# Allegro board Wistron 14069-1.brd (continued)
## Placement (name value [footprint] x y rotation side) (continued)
C9315  SCD22U16V2KX-GP  [C402H22]  83.73 87.94 0 top
C9316  SCD22U16V2KX-GP  [C402H22]  82.72 87.94 0 top
C9317  SCD22U16V2KX-GP  [C402H22]  87.75 87.94 0 top
C9318  SCD22U16V2KX-GP  [C402H22]  86.73 87.94 0 top
C9319  SCD22U16V2KX-GP  [C402H22]  91.78 87.94 0 top
C9320  SCD22U16V2KX-GP  [C402H22]  90.76 87.94 0 top
C9321  SCD1U16V2KX-3GP  [C402H22]  54.42 71.43 0 top
C9322  SCD1U16V2KX-3GP  [C402H22]  55.44 71.43 0 top
C9323  SCD22U16V2KX-GP  [C402H22]  95.8 87.57 0 top
C9324  SCD22U16V2KX-GP  [C402H22]  94.79 87.57 0 top
C9325  SCD22U16V2KX-GP  [C402H22]  101.78 87.94 0 top
C9326  SCD22U16V2KX-GP  [C402H22]  100.76 87.94 0 top
C9327  SCD22U16V2KX-GP  [C402H22]  105.7 87.94 0 top
C9328  SCD22U16V2KX-GP  [C402H22]  104.68 87.94 0 top
C9329  SCD1U16V2KX-3GP  [C402H22]  52.89 86.52 180 top
C9330  SCD1U16V2KX-3GP  [C402H22]  53.87 70.02 90 top
C9331  SCD22U16V2KX-GP  [C402H22]  109.74 87.94 0 top
C9332  SCD22U16V2KX-GP  [C402H22]  108.72 87.94 0 top
C9333  SCD22U16V2KX-GP  [C402H22]  113.7 87.94 0 top
C9334  SCD22U16V2KX-GP  [C402H22]  112.68 87.94 0 top
C9335  SCD22U16V2KX-GP  [C402H22]  116.72 87.94 0 top
C9336  SCD22U16V2KX-GP  [C402H22]  117.73 87.94 0 top
C9337  SCD22U16V2KX-GP  [C402H22]  121.79 87.94 0 top
C9338  SCD22U16V2KX-GP  [C402H22]  120.77 87.94 0 top
C9339  SCD22U16V2KX-GP  [C402H22]  124.62 87.94 0 top
C9340  SCD22U16V2KX-GP  [C402H22]  125.64 87.94 0 top
C9402  SCD1U25V3KX-GP  [C603H36]  42.62 50.05 270 top
C9403  SCD1U25V3KX-GP  [C603H36]  42.62 48.78 270 top
C9404  SCD1U16V2KX-3GP  [C402H22]  56.15 30.96 270 top
C9405  SCD1U16V2KX-3GP  [C402H22]  56.15 29.94 270 top
C9406  SCD1U16V2KX-3GP  [C402H22]  54.18 30.56 90 top
C9407  SCD1U16V2KX-3GP  [C402H22]  54.32 49.45 90 top
C9408  SCD1U16V2KX-3GP  [C402H22]  54.32 50.34 90 top
C9409  SCD1U16V2KX-3GP  [C402H22]  54.16 28.81 90 top
C9410  SCD1U16V2KX-3GP  [C402H22]  53.1 12.55 0 top
C9411  SCD1U16V2KX-3GP  [C402H22]  54.01 12.55 0 top
C9412  SCD1U16V2KX-3GP  [C402H22]  54.89 12.55 0 top
C9413  SCD1U25V3KX-GP  [C603H36]  37.5 17.68 270 top
C9414  SCD1U25V3KX-GP  [C603H36]  37.5 18.95 270 top
C9415  SCD1U16V2KX-3GP  [C402H22]  54.19 29.69 90 top
C9420  SC10P50V2JN-4GP  [C402H22]  221.79 10.74 270 top
C9422  SC10P50V2JN-4GP  [C402H22]  147.88 94.51 0 top
C9902  SCD1U16V2KX-3GP  [C402H22]  47.52 88.82 180 top
C15159  SCD1U16V2ZY-2GP  [C402H22]  193.32 76.78 180 top
C15160  SC1U16V2KX-GP  [C402H22]  187.66 84.84 180 top
C15161  SC1U16V2KX-GP  [C402H22]  190.96 84.81 180 top
CMOS1  PIN-CON3-S-GP  [21S-91-03GB01]  186 7.63 270 top
CPU1  SKYLAKE-1  [SKTBGA1151R754612-UH369]  123.98 163.95 90 top
CRF1  PIN-CON5-SFP2-GP-U  [210-91-05GY21-U]  91 5.5 0 top
D4  SDMK0340L-7-F-GP  [SOD323AKH42]  216.82 50.7 90 top
D20  BAT54A-7-F-2-GP  [SOT23-2D4-312H48]  115.07 33.25 0 top
D21  BAT54A-7-F-2-GP  [SOT23-2D4-312H48]  128.22 30.91 0 top
D2502  BAS40C-2-GP  [SOT-23-9H44]  103.84 19.38 270 top
D2601  1SS355-4-GP  [SOD323AKH38]  145.6 231.88 90 top
D2602  1SS355GP-GP  [SOD323AKH40]  212.3 238.53 270 top
D2603  1SS355GP-GP  [SOD323AKH40]  231.46 36.71 0 top
D2702  DF2B6D8E-1-GP  [D1608AK-UH28]  6.14 47.06 0 top
D2906  BAT54A-7-F-2-GP  [SOT23-2D4-312H48]  13.44 18.05 0 top
D2907  BAT54A-7-F-2-GP  [SOT23-2D4-312H48]  26.34 19.14 0 top
D3001  AZ5125-01H-R7G-GP  [SOD-523-4H28]  9.87 69.52 0 top
D3002  AZ5125-02S-R7G-1-GP  [SOT23-2D4-312H46]  18.49 71.04 0 top
D3003  AZ5125-02S-R7G-1-GP  [SOT23-2D4-312H46]  7.01 69.56 0 top
D3004  AZ5125-01H-R7G-GP  [SOD-523-4H28]  15.62 69.77 0 top
D3005  AZ5125-02S-R7G-1-GP  [SOT23-2D4-312H46]  12.73 69.67 0 top
D3006  AZ5125-01H-R7G-GP  [SOD-523-4H28]  19.14 73.99 90 top
D5601  1SS355-4-GP  [SOD323AKH38]  24.11 228.86 0 top
DBGH1  PIN-CONN14A-SFP1-GP  [220-47-07GB22]  228 105 270 top
DIMM1  DDR4-288P-82-GP  [AH08847-A9L2-4M]  184.43 163.97 270 top
DIMM2  DDR4-288P-82-GP  [AH08847-A9L2-4M]  204.13 163.97 270 top
DIMM3  DDR4-288P-82-GP  [AH08847-A9L2-4M]  176.03 163.97 270 top
DIMM4  DDR4-288P-82-GP  [AH08847-A9L2-4M]  195.73 163.97 270 top
DP1  SKT-DISPLAY20P-25-GP  [105020-0001]  4.2 195 270 top
EC3801  SCD1U16V2KX-3GP  [C402H22]  24.16 170.94 270 top
EC3802  SCD1U16V2KX-3GP  [C402H22]  25.56 152.43 270 top
EC3803  SCD1U16V2KX-3GP  [C402H22]  25.56 153.32 270 top
EC3804  SCD1U16V2KX-3GP  [C402H22]  24.16 171.83 270 top
EC3805  SCD1U16V2KX-3GP  [C402H22]  25.63 150.44 270 top
EC3806  SCD1U16V2KX-3GP  [C402H22]  24.17 173.36 270 top
EC3807  SCD1U16V2KX-3GP  [C402H22]  25.63 149.55 270 top
EC3808  SCD1U16V2KX-3GP  [C402H22]  24.17 174.25 270 top
EC3901  SCD1U16V2KX-3GP  [C402H22]  145.77 20.13 0 top
EC3902  SCD1U16V2KX-3GP  [C402H22]  143.36 20.13 0 top
EC3903  SCD1U16V2KX-3GP  [C402H22]  144.25 20.13 0 top
EC3904  SCD1U16V2KX-3GP  [C402H22]  146.66 20.13 0 top
ED3201  AZC099-04S-R7G-GP  [SOT-6H58]  29.68 114.39 90 top
ED3203  AZC099-04S-R7G-GP  [SOT-6H58]  29.68 118.7 90 top
ED3204  AZC099-04S-R7G-GP  [SOT-6H58]  29.35 105.4 270 top
ED5601  AZ1045-04F-R7G-GP  [DFN10G2510H26]  15.93 218.36 270 top
ED5602  AZ1045-04F-R7G-GP  [DFN10G2510H26]  15.93 213.46 270 top
ED5603  AZ1045-04F-R7G-GP  [DFN10G2510H26]  15.9 225.03 270 top
ED5701  AZ1045-04F-R7G-GP  [DFN10G2510H26]  15.62 195.86 270 top
ED5702  AZ1045-04F-R7G-GP  [DFN10G2510H26]  16.55 191.5 270 top
ED5703  AZ1045-04F-R7G-GP  [DFN10G2510H26]  16.55 187.44 90 top
EL3201  MCM1012B900FBP-GP-U  [L125100-4P-1H37]  33.74 117.69 180 top
EL3202  MCM1012B900FBP-GP-U  [L125100-4P-1H37]  33.74 119.85 180 top
EL3203  MCM1012B900FBP-GP-U  [L125100-4P-1H37]  33.74 115.53 180 top
EL3204  MCM1012B900FBP-GP-U  [L125100-4P-1H37]  33.74 113.37 180 top
EL3603  FILTER-4P-184-GP  [L125100-4P-4H28]  33.77 110.65 180 top
EL3604  FILTER-4P-184-GP  [L125100-4P-4H28]  33.77 108.24 180 top
EL3605  FILTER-4P-184-GP  [L125100-4P-4H28]  162.41 102.15 270 top
EL3701  FILTER-4P-184-GP  [L125100-4P-4H28]  107.29 19.56 270 top
EL3702  FILTER-4P-184-GP  [L125100-4P-4H28]  109.57 19.56 270 top
EL3703  FILTER-4P-184-GP  [L125100-4P-4H28]  87.58 19.41 270 top
EL3801  FILTER-4P-98-GP  [L125100-4P-5H24]  21.52 171.46 270 top
EL3802  MCM1012B900FBP-GP-U  [L125100-4P-1H37]  23.51 169.1 0 top
EL3803  FILTER-4P-98-GP  [L125100-4P-5H24]  21.82 152.43 270 top
EL3804  FILTER-4P-98-GP  [L125100-4P-5H24]  22.54 141.11 270 top
EL3805  MCM1012B900FBP-GP-U  [L125100-4P-1H37]  23.73 147.71 0 top
EL3806  FILTER-4P-98-GP  [L125100-4P-5H24]  22.32 164.72 270 top
EL3807  MCM1012B900FBP-GP-U  [L125100-4P-1H37]  23.73 145.55 0 top
EL3808  MCM1012B900FBP-GP-U  [L125100-4P-1H37]  23.51 166.94 0 top
EL3809  FILTER-4P-98-GP  [L125100-4P-5H24]  21.59 173.81 270 top
EL3810  FILTER-4P-98-GP  [L125100-4P-5H24]  21.75 150.07 270 top
EL3811  FILTER-4P-98-GP  [L125100-4P-5H24]  22.54 143.34 270 top
EL3812  FILTER-4P-98-GP  [L125100-4P-5H24]  22.31 162.49 270 top
EL3901  FILTER-4P-98-GP  [L125100-4P-5H24]  146.1 17.67 0 top
EL3902  FILTER-4P-98-GP  [L125100-4P-5H24]  143.81 17.67 0 top
EL3903  FILTER-4P-98-GP  [L125100-4P-5H24]  139.32 17.65 0 top
EL3904  FILTER-4P-184-GP  [L125100-4P-4H28]  148.28 19.75 270 top
EL3905  FILTER-4P-184-GP  [L125100-4P-4H28]  151.35 19.71 270 top
EL3906  FILTER-4P-98-GP  [L125100-4P-5H24]  141.6 17.65 0 top
EL5601  FILTER-4P-172-GP  [L125100-4PH26]  19.51 212.45 90 top
EL5602  FILTER-4P-172-GP  [L125100-4PH26]  19.51 214.6 90 top
EL5603  FILTER-4P-172-GP  [L125100-4PH26]  19.51 217.22 90 top
EL5604  FILTER-4P-172-GP  [L125100-4PH26]  19.51 219.38 90 top
EL6001  COIL-40OHM-GP  [L125100-4PH26]  221.37 41.53 180 top
EL6002  COIL-40OHM-GP  [L125100-4PH26]  221.37 35.81 180 top
EL6003  COIL-40OHM-GP  [L125100-4PH26]  221.39 27.69 180 top
EL6004  COIL-40OHM-GP  [L125100-4PH26]  221.49 21.08 180 top
EL6005  COIL-40OHM-GP  [L125100-4PH26]  209.65 38.23 180 top
EL6006  COIL-40OHM-GP  [L125100-4PH26]  210.69 44.07 180 top
EL6007  COIL-40OHM-GP  [L125100-4PH26]  210.44 23.11 180 top
EL6008  COIL-40OHM-GP  [L125100-4PH26]  211.18 28.78 180 top
F5601  POLYSW-1D5A8V-4-GP  [POLYSW-3217-UH40]  17.14 231.83 0 top
F5602  POLYSW-1D5A8V-4-GP  [POLYSW-3217-UH40]  12.19 207.52 0 top
FANC1  FOX-CON4-11-GP  [HF1004E]  151 236.82 0 top
FANS1  FOX-CON4-11-GP  [HF1004E]  221.73 237 0 top
FANS2  JWT-CON3-S2-GP  [A2543WV2-3P]  223 237 0 top
FANS3  FOX-CON4-11-GP  [HF1004E]  231 149 270 top
FL2906  0R0603-PAD-2-GP-U  [0R0603-PAD-1-U]  17.46 13.51 0 top
FL2907  0R0603-PAD-2-GP-U  [0R0603-PAD-1-U]  18.86 13.51 0 top
FL2908  0R0603-PAD-2-GP-U  [0R0603-PAD-1-U]  22.52 15.04 0 top
FL2909  0R0603-PAD-2-GP-U  [0R0603-PAD-1-U]  21.17 15.04 0 top
G7901  COPPER-CLOSE-GP-U  [CON2C-U]  234.27 49.01 180 top
GPIO1  JOWLE-CON2-5-GP  [A2541WV0-1EX2PA-6T]  67.3 6.82 90 top
GPIO2  JOWLE-CON2-5-GP  [A2541WV0-1EX2PA-6T]  61.62 6.79 90 top
H1  GENS315R158-8-F-A-GP  [GENS315R158-8-F-A]  33.02 237.65 180 top
H2  GENS315R158-8-F-A-GP  [GENS315R158-8-F-A]  165.1 237.65 180 top
H3  GENS315R158-8-F-A-GP  [GENS315R158-8-F-A]  237.49 237.65 180 top
H4  GENS315R158-8-F-A-GP  [GENS315R158-8-F-A]  237.47 80.17 180 top
H5  GENS315R158-8-F-A-GP  [GENS315R158-8-F-A]  165.1 80.17 180 top
H6  GENS315R158-8-F-A-GP  [GENS315R158-8-F-A]  10.16 80.17 180 top
H7  GENS315R158-8-F-A-GP  [GENS315R158-8-F-A]  10.16 34.45 180 top
H8  GENS315R158-8-F-A-GP  [GENS315R158-8-F-A]  165.1 14.13 180 top
HDMI1  SKT-HDMI23-49-GP  [SKT-HDMI23-150122-10]  3.5 223 270 top
HS1  STF256R109H99-GP  [STF256R109H99]  125.6 98 180 top
HS2  STF256R113-UH258-GP  [STF256R113-UH258]  64.25 58 180 top
HS3  STF256R113-UH258-GP  [STF256R113-UH258]  26.25 58 180 top
JP1  JOWLE-CON2-5-GP  [A2541WV0-1EX2PA-6T]  240.81 63.25 90 top
L2702  PBY201209T-221Y-N-GP  [L20125H44]  8.55 47.21 270 top
L2901  PBY201209T-800Y-N-1GP  [L20125H44]  46.2 10.84 90 top
L3001  MHC1608S601LBP-GP  [L603H38]  7.71 65.3 180 top
L3002  MHC1608S601LBP-GP  [L603H38]  19.18 66.7 180 top
L3003  MHC1608S601LBP-GP  [L603H38]  17.81 66.7 180 top
L3004  MHC1608S601LBP-GP  [L603H38]  13.33 65.4 180 top
L3005  MHC1608S601LBP-GP  [L603H38]  12.01 65.4 180 top
L3006  MHC1608S601LBP-GP  [L603H38]  6.39 65.3 180 top
L3101  COIL-4D7UH-13-GP  [L35301330H103]  31.68 91.59 90 top
L5601  MHC1608S181NBP-GP  [L603H38]  16.81 228.48 90 top
L6401  MHC1608S601LBP-GP  [L603H38]  232.37 11.17 270 top
L6801  FCM1608KFG-301T05-GP  [L1608-UH38]  205.21 10.13 270 top
L7901  MHC1608S181NBP-GP  [L603H38]  238.41 52.44 0 top
LEDH1  TCN-CONN14A-SFP-GP-U  [T11-0063-1A40-0-U]  210.08 6.5 0 top
LEDH2  PIN-CONN14A-SFP5-GP  [210-92-07GB11]  237 20.09 90 top
MECLR1  PIN-CON3-S-GP  [21S-91-03GB01]  196 7.63 270 top
NGFFE1  SKT-NGFF75P-91-GP  [AS0BC21-S40BE-7H]  153.85 98 270 top
NGFFM1  SKT-NGFF75P-90-GP-U  [AS0BC21-S85BM-7H]  103.85 58 270 top
NOREF  -  []  163.3 194.13 0 top
NOREF#2  -  [unnamed#2]  86.48 125.8 0 top
NOREF#3  -  []  94.31 146.66 0 top
NOREF#4  -  [unnamed#2]  52.4 121.45 0 top
NOREF#5  -  [unnamed#2]  161.48 200.8 0 top
NOREF#6  -  [unnamed#2]  140.14 29.37 0 top
NOREF#7  -  [unnamed#2]  239 5 0 top
NOREF#8  -  []  94.41 154.31 0 top
NOREF#9  *  [unnamed#2]  10.73 235.75 0 top
NOREF#10  -  [unnamed#2]  85.63 226.69 0 top
NOREF#11  *  [unnamed#2]  229.94 239.29 0 top
NOREF#12  -  [unnamed#2]  5 5 0 top
NOREF#13  -  []  0 0 0 top
NOREF#14  *  [unnamed#2]  8.54 18.66 0 top
NOREF#15  -  []  0 0 0 top
NOREF#16  -  []  161.14 225.48 0 top
NOREF#17  -  [unnamed#2]  5.59 237.74 0 top
NOREF#18  -  [unnamed#2]  161.48 125.8 0 top
NOREF#19  -  [unnamed#2]  164.14 66.37 0 top
NOREF#20  -  [unnamed#2]  52.4 220.26 0 top
NOREF#21  -  [unnamed#2]  139.57 226.69 0 top
NOREF#22  -  []  0 0 0 top
NOREF#23  -  [unnamed#2]  86.48 200.8 0 top
NOREF#24  -  []  154.48 213.16 180 top
NOREF#25  *  [unnamed#2]  8.54 18.66 180 bottom
NOREF#26  *  [unnamed#2]  229.94 239.29 180 bottom
NOREF#27  *  [unnamed#2]  10.73 235.75 180 bottom
PC301  SC1800P50V2KX-1GP  [C402H22]  183.51 85.34 180 top
PC4602  SC470P50V2KX-3GP  [C402H22]  73.05 216.92 0 top
PC4605  SCD01U50V2KX-1GP  [C402H22]  63.71 218.54 0 top
PC4606  SCD01U50V2KX-1GP  [C402H22]  66.11 214.25 270 top
PC4610  SC68P50V2JN-1GP  [C402H22]  74.13 218.34 270 top
PC4628  SCD01U50V2KX-1GP  [C402H22]  65.17 217.76 270 top
PC4630  SC68P50V2JN-1GP  [C402H22]  72.4 232.19 270 top
PC4631  SC470P50V2KX-3GP  [C402H22]  70.54 235.53 180 top
PC4632  SC2D2U6D3V2MX-GP  [C402H22]  78.27 231.65 90 top
PC4633  SCD01U50V2KX-1GP  [C402H22]  70.61 213.03 0 top
PC4634  SCD01U50V2KX-1GP  [C402H22]  64.59 234.15 270 top
PC4635  SC1U6D3V2KX-GP  [C402H22]  82.37 230.21 0 top
PC4636  SCD22U16V2KX-GP  [C402H22]  58.55 228.35 270 top
PC4637  SCD22U16V2KX-GP  [C402H22]  59.34 221.51 270 top
PC4639  SC180P50V2JN-1GP  [C402H22]  74.45 215 0 top
PC4640  SC180P50V2JN-1GP  [C402H22]  75.87 214.64 270 top
PC4641  SC180P50V2JN-1GP  [C402H22]  75.86 215.52 90 top
PC4642  SC180P50V2JN-1GP  [C402H22]  75.26 234.94 180 top
PC4643  SC180P50V2JN-1GP  [C402H22]  75.7 233.53 90 top
PC4644  SC180P50V2JN-1GP  [C402H22]  76.16 234.95 180 top
PC4645  SCD47U10V2KX-GP  [C402H22]  79.06 221.71 90 top
PC4646  SCD01U50V2KX-1GP  [C402H22]  70.6 234.14 90 top
PC4655  SC1U16V2KX-GP  [C402H22]  79.08 230.71 270 top
PC4666  SCD1U50V2KX-1-GP  [C402H22]  65.37 227.87 0 top
PC4701  SCD01U50V2KX-1GP  [C402H22]  43.43 191.38 270 top
PC4702  SC10U25V6KX-1GP  [C1206H71]  40.51 214.39 270 top
PC4703  SCD1U25V3KX-GP  [C603H36]  42.91 219.16 90 top
PC4704  SC1U16V2KX-GP  [C402H22]  50.12 215.98 180 top
PC4705  SC1KP50V2KX-1GP  [C402H22]  60.71 195.58 0 top
PC4706  SCD1U25V3KX-GP  [C603H36]  44.99 196.91 90 top
PC4707  SC10U25V6KX-1GP  [C1206H71]  43.43 193.09 270 top
PC4708  SC1U16V2KX-GP  [C402H22]  51.17 195.48 180 top
PC4709  SC1KP50V2KX-1GP  [C402H22]  60.63 173.99 0 top
PC4710  SCD1U25V3KX-GP  [C603H36]  44.99 174.96 90 top
PC4711  SC10U25V6KX-1GP  [C1206H71]  43.43 170.28 270 top
PC4712  SC1U16V2KX-GP  [C402H22]  51.04 173.76 180 top
PC4713  SC1KP50V2KX-1GP  [C402H22]  60.66 152.32 0 top
PC4716  SCD01U50V2KX-1GP  [C402H22]  40.51 212.65 270 top
PC4717  SCD01U50V2KX-1GP  [C402H22]  43.43 168.55 270 top
PC4720  SCD47U10V2KX-GP  [C402H22]  66.6 217.47 180 top
PC4721  SCD47U10V2KX-GP  [C402H22]  67.51 214.72 0 top
PC4722  SCD47U10V2KX-GP  [C402H22]  64.66 219.92 0 top
PC4723  SCD47U10V2KX-GP  [C402H22]  70.99 214.44 270 top
PC4734  SCD1U25V3KX-GP  [C603H36]  44.64 153.47 90 top
PC4735  SCD01U50V2KX-1GP  [C402H22]  43.43 147.74 270 top
PC4736  SC10U25V6KX-1GP  [C1206H71]  43.43 149.44 270 top
PC4737  SC1KP50V2KX-1GP  [C402H22]  60.66 130.56 0 top
PC4801  SC10U25V6KX-1GP  [C1206H71]  100.98 235.55 180 top
PC4802  SCD1U25V3KX-GP  [C603H36]  89.42 220.62 0 top
PC4803  SCD01U50V2KX-1GP  [C402H22]  102.59 235.55 180 top
PC4804  SC1KP50V2KX-1GP  [C402H22]  93.95 217.5 270 top
PC4805  SC1U16V2KX-GP  [C402H22]  90.07 211.1 90 top
PC4806  SCD1U25V3KX-GP  [C603H36]  133.51 235.64 0 top
PC4807  SCD01U50V2KX-1GP  [C402H22]  116.26 235.55 180 top
PC4808  SC10U25V6KX-1GP  [C1206H71]  114.64 235.55 180 top
PC4809  SC1U16V2KX-GP  [C402H22]  133.02 227.18 0 top
PC4810  SC1KP50V2KX-1GP  [C402H22]  131.27 217.73 90 top
PC4812  SCD47U10V2KX-GP  [C402H22]  66.6 232.2 90 top
PC4813  SCD47U10V2KX-GP  [C402H22]  68.69 233.34 270 top
PC5002  SC1U6D3V2KX-GP  [C402H22]  229.48 112.87 90 top
PC5003  SC1U6D3V2KX-GP  [C402H22]  227.85 116.97 180 top
PC5004  SC10U25V6KX-1GP  [C1206H71]  219.81 123.72 90 top
PC5005  SCD1U25V3KX-GP  [C603H36]  225.2 120.08 0 top
PC5006  SC10U10V3MX-GP  [C603H36]  221.27 120.21 180 top
PC5007  SCD1U16V2KX-3GP  [C402H22]  212.57 145.85 180 top
PC5009  SC10U6D3V3MX-GP  [C603H38]  218.93 117.16 0 top
PC5010  SC10U6D3V3MX-LL-GP  [C603H36]  217.72 117.17 0 top
PC5011  SC1KP50V2KX-1GP  [C402H22]  218.11 129.2 0 top
PC5012  SCD033U16V2KX-GP  [C402H22]  217.78 113.78 270 top
PC5013  SC22P50V2JN-4-LL-GP  [C402H22]  219.51 111.4 0 top
PC5020  SCD01U50V2KX-1GP  [C402H22]  217.72 127.78 90 top
PC5033  SC10U10V5KX-2DLGP  [C805H50]  180.64 74.09 180 top
PC5034  SC10U10V5KX-2DLGP  [C805H50]  182.6 74.09 180 top
PC5035  SC1U10V2KX-1DLGP  [C402H22]  173.88 71.7 270 top
PC5036  SC22U6D3V5MX-2DLGP  [C805H54]  174.57 83.95 0 top
PC5037  SC22U6D3V5MX-2DLGP  [C805H54]  172.64 83.95 0 top
PC5038  SC3D3P50V2CN-DL-GP  [C402H22]  171.15 74.22 0 top
PC5039  SC680P50V2KX-2DLGP  [C402H22]  173.1 73.18 0 top
PC5040  SC1U10V2KX-1DLGP  [C402H22]  231.24 223.98 0 top
PC5041  SCD1U16V2KX-3DLGP  [C402H22]  173.51 76.96 180 top
PC5101  SC10U6D3V3MX-GP  [C603H38]  182.64 42.68 90 top
PC5102  SC10U25V6KX-1GP  [C1206H71]  203.27 45.19 0 top
PC5103  SC10U25V6KX-1GP  [C1206H71]  201.02 45.22 0 top
PC5105  SCD1U25V3KX-GP  [C603H36]  193.17 36.96 90 top
PC5106  SCD1U16V2KX-3GP  [C402H22]  202.57 33.96 180 top
PC5108  SC1KP50V2KX-1GP  [C402H22]  185.58 55.42 180 top
PC5109  SC1U6D3V2KX-GP  [C402H22]  194.21 38.15 270 top
PC5110  SC22P50V2JN-4-LL-GP  [C402H22]  202.93 37.31 270 top
PC5111  SCD1U16V2KX-3GP  [C402H22]  204.97 39.01 0 top
PC5201  SC2K2P50V3KX-GP  [C603]  73.45 105.54 270 top
PC5202  SC1U10V2KX-1GP  [C402H22]  58.15 110.01 90 top
PC5203  SC1U10V2KX-1GP  [C402H22]  59.33 106.81 90 top
PC5204  SC10U25V6KX-1GP  [C1206H71]  62.79 100.48 270 top
PC5205  SCD1U25V3KX-GP  [C603H36]  56.11 110.96 0 top
PC5206  SCD1U16V2KX-3GP  [C402H22]  80.9 113.56 90 top
PC5207  SCD022U25V2KX-GP  [C402H22]  52.48 104.52 180 top
PC5208  SC100P50V2JN-3GP  [C402H22]  51.07 103.94 270 top
PC5209  SC1KP50V2JN-2GP  [C402H22]  50.81 102.41 0 top
PC5210  SCD022U25V2KX-GP  [C402H22]  57.79 104.16 0 top
PC5211  SCD1U25V2KX-2-GP  [C402H22]  56.87 102.96 0 top
PC5219  SCD1U50V2KX-1-GP  [C402H22]  51 107.86 270 top
PC5268  SC470P50V2JN-GP  [C402H22]  51 105.97 270 top
PC5301  SC10U25V5KX-GP  [C805H56]  100.01 100.12 0 top
PC5302  SC10U25V5KX-GP  [C805H56]  112.48 100.02 0 top
PC5303  SC10U25V5KX-GP  [C805H56]  110.44 100.02 0 top
PC5304  SCD1U25V2KX-2-GP  [C402H22]  113.91 99.93 0 top
PC5305  SCD1U25V2KX-2-GP  [C402H22]  117.55 100.43 0 top
PC5306  SCD1U25V2KX-2-GP  [C402H22]  101.43 100.36 0 top
PC5307  SC1U16V3KX-2GP  [C603H36]  119.76 98.58 90 top
PC5308  SC1KP50V2KX-1GP  [C402H22]  117.35 103.44 0 top
PC5309  SC18P50V2JN-1-GP  [C402H22]  119.56 91.36 180 top
PC5310  SC10U25V5KX-GP  [C805H56]  108.43 100.03 0 top
PC5311  SC1U6D3V2KX-LL-GP  [C402H22]  116.65 90.57 0 top
PC5427  SC10U25V6KX-1GP  [C1206H71]  219.35 125.93 90 top
PC5438  SC1U16V2KX-GP  [C402H22]  51.16 152.07 180 top
PCH1  SUNRISE-1-GP  [BGA837M23-1H58]  152.2 48 180 top
PCIE1  PCISLT36-7-GP  [AAA-PCI-003-K45]  57 39.69 0 top
PCIE2  PCISLT36-7-GP  [AAA-PCI-003-K45]  57.04 19.27 0 top
PCIE16  T-CONN164-4R4-GP  [4-1470780-7]  57.03 80.33 0 top
PD5001  SSM34GP-GP  [D5126145AKH91]  209.72 110.07 180 top
PD5002  SSM34GP-GP  [D5126145AKH91]  213.37 110.07 180 top
PD5101  SSM34GP-GP  [D5126145AKH91]  189.69 57.67 90 top
PD5102  SSM34GP-GP  [D5126145AKH91]  189.69 61.33 90 top
PG4699  GAP-OPEN-PWR-2-GP  [GAP-OPEN-PWR-2]  59.89 214.34 270 top
PG4701  COPPER-CLOSE-GP-U  [CON2C-U]  60.51 185.35 90 top
PG4702  COPPER-CLOSE-GP-U  [CON2C-U]  60.51 207.02 90 top
PG4703  COPPER-CLOSE-GP-U  [CON2C-U]  66.09 207.02 270 top
PG4704  COPPER-CLOSE-GP-U  [CON2C-U]  66.09 185.35 270 top
PG4705  COPPER-CLOSE-GP-U  [CON2C-U]  60.51 163.63 90 top
PG4706  COPPER-CLOSE-GP-U  [CON2C-U]  66.09 163.63 270 top
PG4801  COPPER-CLOSE-GP-U  [CON2C-U]  104.78 216.92 45 top
PG4802  COPPER-CLOSE-GP-U  [CON2C-U]  106.17 215.52 225 top
PG4803  COPPER-CLOSE-GP-U  [CON2C-U]  118.15 216.91 45 top
PG4804  COPPER-CLOSE-GP-U  [CON2C-U]  119.55 215.51 225 top
PG5001  GAP-CLOSE-PWR-3-GP  [GAP-CLOSE-PWR-3]  223.96 149.24 270 top
PG5101  GAP-CLOSE-PWR-3-GP  [GAP-CLOSE-PWR-3]  180.11 50.11 270 top
PG5201  COPPER-CLOSE-GP-U  [CON2C-U]  83.09 106.47 180 top
PG5202  COPPER-CLOSE-GP-U  [CON2C-U]  83.09 109.72 0 top
PG5203  COPPER-CLOSE-GP-U  [CON2C-U]  60.51 141.95 90 top
PG5204  COPPER-CLOSE-GP-U  [CON2C-U]  66.09 141.95 270 top
PL12  IND-1D5UH-53-GP-U  [L686647-127318H119]  179.32 82.85 180 top
PL4701  IND-D36UH-54-GP  [L112100-2135H158]  63.3 207.02 90 top
PL4702  IND-D36UH-54-GP  [L112100-2135H158]  63.3 185.35 90 top
PL4703  IND-D36UH-54-GP  [L112100-2135H158]  63.3 163.63 90 top
PL4704  IND-D36UH-54-GP  [L112100-2135H158]  63.3 141.95 90 top
PL4801  COIL-D36UH-11-GP  [RT-D6-4D5-1010H375]  105.81 216.56 90 top
PL4802  COIL-D36UH-11-GP  [RT-D6-4D5-1010H375]  119.36 216.57 90 top
PL5001  COIL-1D2UH-42-GP  [RT-D6D2-108108H426]  219.48 142.47 270 top
PL5101  IND-1D5UH-53-GP-U  [L686647-127318H119]  185.49 47.12 270 top
PL5203  IND-D68UH-36-GP-U  [L686647-127318H119]  83.09 108.1 180 top
PL5301  IND-2D2UH-122-GP-U  [L686647-127318H119]  115.6 113.79 270 top
PN4603  NTC-100K-11-GP-U  [NTC-402H24-U]  53.19 200.53 0 top
PN4604  NTC-100K-11-GP-U  [NTC-402H24-U]  97.47 226.07 270 top
PN4605  NTC-100K-11-GP-U  [NTC-402H24-U]  112.54 216.65 0 top
PN4606  NTC-100K-11-GP-U  [NTC-402H24-U]  57.78 214.29 270 top
PR302  2D2R5J-1-GP  [R805H24]  184.15 82.55 180 top
PR977  0R0402-PAD-2-GP  [0R0402-PAD-1]  173.77 75.49 90 top
PR4601  100KR2F-L1-GP  [R402H16]  76.79 231.4 180 top
PR4602  3K9R2F-GP  [R402H16]  75.05 216.93 0 top
PR4603  30KR2F-GP  [R402H16]  74.01 216.93 180 top
PR4604  0R0805-PAD-2-GP-U  [0R0805-PAD-1-U]  80.5 234.45 270 top
PR4611  680R2F-GP  [R402H16]  67.11 218.97 270 top
PR4616  100R2J-2-GP  [R402H14]  73.01 213.53 270 top
PR4621  680R2F-GP  [R402H16]  70.33 216.44 270 top
PR4622  680R2F-GP  [R402H16]  67.11 220 270 top
PR4623  680R2F-GP  [R402H16]  69.52 214.97 0 top
PR4629  280R2F-1-GP  [R402H16]  73.87 232.22 180 top
PR4630  33KR2F-GP  [R402H16]  72.4 233.14 270 top
PR4632  10K2R2F-GP  [R402H16]  78.79 224.76 270 top
PR4633  0R0402-PAD-2-GP  [0R0402-PAD-1]  73.22 235.19 180 top
PR4635  100R2J-2-GP  [R402H14]  74.26 235.52 180 top
PR4639  680R2F-GP  [R402H16]  65.07 232.75 180 top
PR4640  60K4R2F-GP  [R402H16]  77.34 211.8 180 top
PR4641  32D4R2F-GP  [R402H16]  77.34 213.68 180 top
PR4642  16KR2F-GP  [R402H16]  77.83 215.24 90 top
PR4643  1K3R2F-1-GP  [R402H16]  78.38 212.9 0 top
PR4644  68KR2F-GP  [R402H16]  80.52 210.36 180 top
PR4645  2K26R2F-1-GP  [R402H16]  80.49 213.18 180 top
PR4646  16K5R2F-2-GP  [R402H16]  83.5 222.06 180 top
PR4647  309R2F-GP  [R402H16]  78.81 211.36 270 top
PR4648  6K34R2F-GP  [R402H16]  82.04 223.24 270 top
PR4649  20R2F-GP  [R402H16]  82.04 222.22 270 top
PR4650  3K32R2F-GP  [R402H16]  80.2 215.65 90 top
PR4651  169KR2F-1-GP  [R402H16]  82.92 214.63 270 top
PR4652  680R2F-GP  [R402H16]  70.2 232.76 180 top
PR4653  910R2F-1-GP  [R402H16]  80.71 216.66 270 top
PR4654  18K7R2F-GP  [R402H16]  80.73 217.69 90 top
PR4655  274R2F-GP  [R402H16]  82.62 217.69 90 top
PR4656  2K8R2F-GP  [R402H16]  79.08 220.76 270 top
PR4657  12KR2F-L-GP  [R402H16]  79.38 218.7 90 top
PR4658  3K24R2F-GP  [R402H16]  81.04 214.63 270 top
PR4659  0R0402-PAD-2-GP  [0R0402-PAD-1]  82.62 218.7 270 top
PR4660  82R2F-GP  [R402H14]  81.97 220.76 270 top
PR4661  430KR2F-GP  [R402H16]  58.55 226.95 0 top
PR4662  2D2R5J-1-GP  [R805H24]  57.12 222.48 0 top
PR4663  499KR5F-2-GP  [R805H24]  59.94 223.7 90 top
PR4664  1R2J-GP  [R402H16]  78.6 223.2 0 top
PR4665  10KR2F-2-GP  [R402H16]  64.01 232.75 180 top
PR4666  3K09R2F-1-GP  [R402H16]  80.02 219.74 270 top
PR4667  18KR2F-GP  [R402H16]  79.47 213.18 0 top
PR4668  2D2R5J-1-GP  [R805H24]  57.07 226.04 180 top
PR4669  12K4R2F-GP  [R402H16]  80.53 221.18 0 top
PR4670  49D9R2F-GP  [R402H16]  78.85 229.74 90 top
PR4671  10KR2F-2-GP  [R402H16]  72.17 234.95 180 top
PR4672  51KR2F-L-GP  [R402H16]  65.06 222.17 90 top
PR4673  300KR3F-GP  [R603H22]  62.3 222.14 90 top
PR4674  8K66R2F-GP  [R402H16]  62.63 221.02 90 top
PR4675  300KR3F-GP  [R603H22]  63.92 230.47 90 top
PR4676  51KR2F-L-GP  [R402H16]  66.24 230.43 90 top
PR4677  8K66R2F-GP  [R402H16]  64.32 229.34 90 top
PR4678  75R2F-2-GP  [R402H16]  78.42 226.21 0 top
PR4679  45D3R2F-L-GP  [R402H16]  80.99 230.82 270 top
PR4680  100R2F-L1-GP-U  [R402H14]  80.98 229.78 90 top
PR4681  75R2F-2-GP  [R402H16]  80.91 226.82 90 top
PR4682  100KR2F-L1-GP  [R402H16]  58.47 94.94 90 top
PR4683  127KR2F-GP  [R402H16]  66.33 227.87 180 top
PR4684  510KR2F-GP  [R402H16]  64.4 227.87 180 top
PR4685  100R2F-L1-GP-U  [R402H14]  75.87 213.69 90 top
PR4686  43KR2F-GP  [R402H16]  81.92 219.74 270 top
PR4687  165KR2F-GP  [R402H16]  82.99 216.66 270 top
PR4688  100R2F-L1-GP-U  [R402H14]  77.18 234.96 0 top
PR4689  0R0402-PAD-2-GP  [0R0402-PAD-1]  78.19 234.85 180 top
PR4690  10K5R2F-GP  [R402H16]  83.43 220.18 180 top
PR4691  10R2F-L-GP  [R402H14]  78.86 228.7 90 top
PR4692  0R0402-PAD-2-GP  [0R0402-PAD-1]  78.86 227.66 270 top
PR4693  0R2J-2-GP  [R402H16]  72.1 218.57 270 top
PR4694  10KR2F-2-GP  [R402H16]  70.32 217.48 270 top
PR4695  0R2J-2-GP  [R402H16]  66.01 225.25 270 top
PR4702  2D2R5J-1-GP  [R805H24]  43.38 222.06 90 top
PR4703  2D2R5J-1-GP  [R805H24]  46.94 222.06 270 top
PR4704  10KR2J-3-GP  [R402H16]  57.56 213.04 90 top
PR4705  2D2R6J-3-GP  [R1206H28]  61.16 199.11 0 top
PR4706  2D2R5J-1-GP  [R805H24]  52.39 215.53 90 top
PR4707  2D2R5J-1-GP  [R805H24]  45.34 200 90 top
PR4708  2D2R5J-1-GP  [R805H24]  48.92 200 270 top
PR4709  10KR2J-3-GP  [R402H16]  57.56 191.37 90 top
PR4711  2D2R5J-1-GP  [R805H24]  52.65 194.37 0 top
PR4712  2D2R6J-3-GP  [R1206H28]  61.16 177.4 0 top
PR4713  2D2R5J-1-GP  [R805H24]  45.23 178.03 90 top
PR4714  2D2R5J-1-GP  [R805H24]  48.79 178.03 270 top
PR4715  10KR2J-3-GP  [R402H16]  57.56 169.65 90 top
PR4717  2D2R6J-3-GP  [R1206H28]  61.16 155.7 0 top
PR4718  2D2R5J-1-GP  [R805H24]  52.64 172.65 0 top
PR4720  0R0805-PAD-2-GP-U  [0R0805-PAD-1-U]  49.68 225.93 180 top
PR4721  0R0805-PAD-2-GP-U  [0R0805-PAD-1-U]  47.75 225.93 180 top
PR4722  0R0805-PAD-2-GP-U  [0R0805-PAD-1-U]  45.82 225.93 180 top
PR4723  0R0805-PAD-2-GP-U  [0R0805-PAD-1-U]  43.89 225.93 180 top
PR4724  0R0805-PAD-2-GP-U  [0R0805-PAD-1-U]  41.96 225.93 180 top
PR4725  0R0805-PAD-2-GP-U  [0R0805-PAD-1-U]  40.03 225.93 180 top
PR4726  976R2F-3-GP  [R402H16]  65.12 216.57 90 top
PR4727  680R2F-GP  [R402H16]  67.55 217.49 0 top
PR4728  976R2F-3-GP  [R402H16]  66.12 215.21 90 top
PR4729  680R2F-GP  [R402H16]  68.49 214.97 180 top
PR4730  976R2F-3-GP  [R402H16]  63.26 220 90 top
PR4731  680R2F-GP  [R402H16]  65.61 219.9 180 top
PR4732  976R2F-3-GP  [R402H16]  71.56 213.04 180 top
PR4733  680R2F-GP  [R402H16]  70.99 215.4 90 top
PR4741  10KR2J-3-GP  [R402H16]  46.56 214.96 90 top
PR4742  10KR2J-3-GP  [R402H16]  49.15 215.21 180 top
PR4743  10KR2J-3-GP  [R402H16]  47.37 192.84 90 top
PR4744  10KR2J-3-GP  [R402H16]  51.16 193.55 180 top
PR4745  10KR2J-3-GP  [R402H16]  47.37 170.81 90 top
PR4746  10KR2J-3-GP  [R402H16]  51.05 171.83 180 top
PR4747  10KR2J-3-GP  [R402H16]  47.37 149.2 90 top
PR4748  10KR2J-3-GP  [R402H16]  51.1 150.14 180 top
PR4752  2D2R5J-1-GP  [R805H24]  49.98 156.49 270 top
PR4754  2D2R6J-3-GP  [R1206H28]  61.16 133.95 0 top
PR4755  2D2R5J-1-GP  [R805H24]  45.23 156.49 90 top
PR4801  2D2R5J-1-GP  [R805H24]  87.87 220.85 0 top
PR4802  0R0805-PAD-2-GP-U  [0R0805-PAD-1-U]  95.7 234.96 180 top
PR4803  0R0805-PAD-2-GP-U  [0R0805-PAD-1-U]  97.66 234.96 180 top
PR4804  2D2R5J-1-GP  [R805H24]  85.94 220.85 0 top
PR4805  0R0805-PAD-2-GP-U  [0R0805-PAD-1-U]  89.85 234.96 180 top
PR4806  0R0805-PAD-2-GP-U  [0R0805-PAD-1-U]  93.74 234.96 180 top
PR4807  0R0805-PAD-2-GP-U  [0R0805-PAD-1-U]  91.79 234.96 180 top
PR4808  10KR2J-3-GP  [R402H16]  112.45 221.52 0 top
PR4810  2D2R6J-3-GP  [R1206H28]  97.35 218 270 top
PR4811  2D2R5J-1-GP  [R805H24]  84.84 213.79 180 top
PR4812  2D2R5J-1-GP  [R805H24]  128.04 236.52 0 top
PR4813  2D2R5J-1-GP  [R805H24]  130.81 236.38 270 top
PR4814  10KR2J-3-GP  [R402H16]  125.94 223.28 0 top
PR4816  2D2R6J-3-GP  [R1206H28]  127.88 218.04 90 top
PR4817  2D2R5J-1-GP  [R805H24]  130.76 227.18 270 top
PR4820  1K2R2F-1-GP  [R402H16]  66.6 234.36 90 top
PR4821  680R2F-GP  [R402H16]  66.6 233.22 90 top
PR4822  1K2R2F-1-GP  [R402H16]  68.69 234.29 270 top
PR4823  680R2F-GP  [R402H16]  68.69 232.32 270 top
PR4825  10KR2J-3-GP  [R402H16]  87.99 212.42 90 top
PR4826  10KR2J-3-GP  [R402H16]  88.04 210.95 0 top
PR4827  10KR2J-3-GP  [R402H16]  129.67 229.13 90 top
PR4828  10KR2J-3-GP  [R402H16]  131.57 229.13 90 top
PR5001  0R0402-PAD-2-GP  [0R0402-PAD-1]  217.91 112.39 90 top
PR5002  2D2R5J-1-GP  [R805H24]  227.32 114.18 180 top
PR5003  11K5R2F-GP  [R402H16]  226.85 116.97 180 top
PR5008  620KR2F-GP  [R402H16]  223.28 111.36 180 top
PR5009  100KR2J-1-GP  [R402H16]  224.32 111.36 180 top
PR5010  2D2R5J-1-GP  [R805H24]  223.09 121.51 0 top
PR5011  2D2R5J-1-GP  [R805H24]  211.58 137.42 180 top
PR5012  2D2R5F-2-GP  [R805H24]  217.72 132.71 0 top
PR5013  0R0805-PAD-2-GP-U  [0R0805-PAD-1-U]  216.1 116.66 180 top
PR5015  8K2R2F-1-GP  [R402H16]  220.45 111.4 0 top
PR5016  0R0805-PAD-2-GP-U  [0R0805-PAD-1-U]  217.55 159.26 180 top
PR5017  0R0805-PAD-2-GP-U  [0R0805-PAD-1-U]  219.58 159.26 180 top
PR5018  13K3R2F-L1-GP  [R402H16]  221.46 111.4 0 top
PR5019  0R0805-PAD-2-GP-U  [0R0805-PAD-1-U]  221.62 159.26 180 top
PR5020  0R0805-PAD-2-GP-U  [0R0805-PAD-1-U]  223.65 159.26 180 top
PR5021  0R0805-PAD-2-GP-U  [0R0805-PAD-1-U]  218.87 119.66 90 top
PR5022  0R0805-PAD-2-GP-U  [0R0805-PAD-1-U]  215.52 159.26 180 top
PR5023  0R0805-PAD-2-GP-U  [0R0805-PAD-1-U]  213.49 159.26 180 top
PR5024  0R0805-PAD-2-GP-U  [0R0805-PAD-1-U]  185.39 75.03 270 top
PR5025  0R0805-PAD-2-GP-U  [0R0805-PAD-1-U]  185.39 73.06 270 top
PR5026  0R0805-PAD-2-GP-U  [0R0805-PAD-1-U]  170.69 89.15 180 top
PR5027  0R0805-PAD-2-GP-U  [0R0805-PAD-1-U]  168.66 89.15 180 top
PR5101  0R0805-PAD-2-GP-U  [0R0805-PAD-1-U]  176.68 51.19 270 top
PR5102  0R0805-PAD-2-GP-U  [0R0805-PAD-1-U]  194.51 57.38 180 top
PR5103  0R0805-PAD-2-GP-U  [0R0805-PAD-1-U]  196.44 57.38 180 top
PR5104  10KR2J-3-GP  [R402H16]  201.61 33.97 180 top
PR5105  100KR2J-1-GP  [R402H16]  203.94 35.83 180 top
PR5106  2D2R5J-1-GP  [R805H24]  193.04 35.31 90 top
PR5107  2D2R5J-1-GP  [R805H24]  194.17 48.19 270 top
PR5108  10KR2J-3-GP  [R402H16]  204.98 35.83 180 top
PR5109  49K9R2F-L-GP  [R402H16]  201.73 36.27 90 top
PR5110  470KR2F-GP  [R402H16]  201.24 39.67 0 top
PR5111  2D2R5F-2-GP  [R805H24]  185.57 52.67 180 top
PR5112  2D2R5J-1-GP  [R805H24]  193.42 39.62 270 top
PR5113  10KR2F-2-GP  [R402H16]  202.91 38.26 270 top
PR5114  0R0805-PAD-2-GP-U  [0R0805-PAD-1-U]  176.68 43.47 270 top
PR5115  0R0805-PAD-2-GP-U  [0R0805-PAD-1-U]  176.68 45.4 270 top
PR5116  0R0805-PAD-2-GP-U  [0R0805-PAD-1-U]  176.68 47.33 270 top
PR5117  0R0805-PAD-2-GP-U  [0R0805-PAD-1-U]  176.68 49.26 270 top
PR5118  22KR2F-GP  [R402H16]  202.72 39.32 90 top
PR5142  5D1R2F-GP  [R402H16]  177.62 72.42 270 top
PR5143  162KR2F-L-GP  [R402H16]  172.14 74.21 0 top
PR5144  10KR2F-2-GP  [R402H16]  172.54 76.94 0 top
PR5145  51KR2F-L-GP  [R402H16]  174.12 73.18 0 top
PR5146  18KR2F-GP  [R402H16]  172.14 72.22 0 top
PR5201  49K9R2F-L-GP  [R402H16]  59.79 104.36 180 top
PR5202  2D2R5J-1-GP  [R805H24]  58.96 111.46 270 top
PR5203  2D2R5J-1-GP  [R805H24]  59.73 108.37 270 top
PR5204  10KR2J-3-GP  [R402H16]  51 106.91 90 top
PR5205  0R0805-PAD-2-GP-U  [0R0805-PAD-1-U]  54.48 110.72 180 top
PR5206  2D2R5J-1-GP  [R805H24]  52.51 110.09 180 top
PR5207  49K9R2F-L-GP  [R402H16]  59.31 105.83 90 top
PR5208  1R5J-2-GP  [R805H24]  76.65 105.54 270 top
PR5209  6K98R2F-GP  [R402H16]  51.07 104.96 270 top
PR5210  0R0402-PAD-2-GP  [0R0402-PAD-1]  54.27 103.32 90 top
PR5211  9K53R2F-GP  [R402H16]  52.79 102.41 0 top
PR5212  10KR2F-2-GP  [R402H16]  58.76 104.17 0 top
PR5213  3KR2F-GP  [R402H16]  51.77 102.41 0 top
PR5214  100R2F-L1-GP-U  [R402H14]  53.55 100.9 270 top
PR5215  100R2F-L1-GP-U  [R402H14]  51.66 100.9 90 top
PR5216  100R2F-L1-GP-U  [R402H14]  55.29 102.29 270 top
PR5217  0R0805-PAD-2-GP-U  [0R0805-PAD-1-U]  63.66 97.58 0 top
PR5218  0R0805-PAD-2-GP-U  [0R0805-PAD-1-U]  65.69 97.58 0 top
PR5219  0R0805-PAD-2-GP-U  [0R0805-PAD-1-U]  67.72 97.58 0 top
PR5301  0R0402-PAD-2-GP  [0R0402-PAD-1]  117.59 90.57 0 top
PR5302  0R0805-PAD-2-GP-U  [0R0805-PAD-1-U]  103.35 100.1 0 top
PR5303  0R0805-PAD-2-GP-U  [0R0805-PAD-1-U]  105.29 100.1 0 top
PR5304  10KR2J-3-GP  [R402H16]  114.61 91.24 180 top
PR5305  2D2R5J-1-GP  [R805H24]  115.93 99.83 180 top
PR5306  2D2R5J-1-GP  [R805H24]  108.58 107.11 180 top
PR5307  34KR2F-GP  [R402H16]  115.65 90.22 0 top
PR5308  470KR2F-GP  [R402H16]  120.52 94.42 180 top
PR5309  2D2R5J-1-GP  [R805H24]  116.84 106.19 0 top
PR5310  100R2F-L1-GP-U  [R402H14]  120.98 90.9 90 top
PR5311  2D2R5J-1-GP  [R805H24]  120.07 100.13 90 top
PR5312  11K8R2F-GP  [R402H16]  120.98 91.92 270 top
PR5313  0R0805-PAD-2-GP-U  [0R0805-PAD-1-U]  98.96 105.29 270 top
PR5314  0R0805-PAD-2-GP-U  [0R0805-PAD-1-U]  98.96 107.25 270 top
PR5315  0R0805-PAD-2-GP-U  [0R0805-PAD-1-U]  98.96 109.2 270 top
PR5316  33KR2F-GP  [R402H16]  120.98 92.96 90 top
PR5317  100R2F-L1-GP-U  [R402H14]  121.54 94.42 180 top
PR5318  0R0402-PAD-2-GP  [0R0402-PAD-1]  122.88 91.03 270 top
PR5319  0R0402-PAD-2-GP  [0R0402-PAD-1]  122.88 92.96 270 top
PR5320  0R0402-PAD-2-GP  [0R0402-PAD-1]  113.59 91.24 0 top
PR5321  0R0805-PAD-2-GP-U  [0R0805-PAD-1-U]  98.96 103.35 270 top
PR5413  0R0402-PAD-2-GP  [0R0402-PAD-1]  73.07 215.44 270 top
PR5453  10KR2J-3-GP  [R402H16]  57.56 147.97 90 top
PR5456  2D2R5J-1-GP  [R805H24]  52.64 151.11 0 top
PR5458  0R0402-PAD-2-GP  [0R0402-PAD-1]  82.92 215.65 270 top
PT1  E820U2D5VM-8-GP  [ECAP-100D6D3H355]  164.44 176.76 90 top
PT2  E820U2D5VM-8-GP  [ECAP-100D6D3H355]  164.52 168.86 90 top
PT4701  E820U2D5VM-8-GP  [ECAP-100D6D3H355]  76.8 189.72 90 top
PT4702  E270U16VM-16-GP  [ECAP-138D8-UH355]  40.43 207.31 90 top
PT4703  E820U2D5VM-8-GP  [ECAP-100D6D3H355]  76.29 158.72 90 top
PT4704  E820U2D5VM-8-GP  [ECAP-100D6D3H355]  78.98 182.05 90 top
PT4705  E820U2D5VM-8-GP  [ECAP-100D6D3H355]  79.19 174.07 90 top
PT4706  E820U2D5VM-8-GP  [ECAP-100D6D3H355]  79.29 166.08 90 top
PT4707  E270U16VM-16-GP  [ECAP-138D8-UH355]  40.43 186.06 90 top
PT4708  E270U16VM-16-GP  [ECAP-138D8-UH355]  40.43 163.23 90 top
PT4709  E270U16VM-16-GP  [ECAP-138D8-UH355]  40.43 142.37 90 top
PT4801  E820U2D5VM-8-GP  [ECAP-100D6D3H355]  102.96 206.63 90 top
PT4802  E270U16VM-16-GP  [ECAP-138D8-UH355]  108.39 237.61 90 top
PT4803  E820U2D5VM-8-GP  [ECAP-100D6D3H355]  127.64 206.63 90 top
PT4804  E820U2D5VM-8-GP  [ECAP-100D6D3H355]  119.23 206.5 90 top
PT4805  E820U2D5VM-8-GP  [ECAP-100D6D3H355]  111.07 206.58 90 top
PT4806  E820U2D5VM-8-GP  [ECAP-100D6D3H355]  94.84 206.65 90 top
PT4807  E270U16VM-16-GP  [ECAP-138D8-UH355]  121.81 237.56 90 top
PT5004  E270U16VM-16-GP  [ECAP-138D8-UH355]  212.7 122.58 0 top
PT5101  E270U16VM-16-GP  [ECAP-138D8-UH355]  204.12 52.27 0 top
PT5107  E820U2D5VM-8-GP  [ECAP-100D6D3H355]  180.77 55.35 0 top
PT5201  E270U16VM-16-GP  [ECAP-138D8-UH355]  66.2 106.21 0 top
PT5202  E820U2D5VM-8-GP  [ECAP-100D6D3H355]  92.61 117.78 0 top
PT5203  E820U2D5VM-8-GP  [ECAP-100D6D3H355]  90.88 109.94 0 top
PT5204  E820U2D5VM-8-GP  [ECAP-100D6D3H355]  100.99 117.96 0 top
PU51  RT8068AZQWID-GP-U  [DFN10G3-G265175H32]  177.14 75.44 0 top
PU4002  ME2N7002E-G-GP  [SOT23DGS2D4H44]  113.1 49.75 270 top
PU4003  ME2N7002E-G-GP  [SOT23DGS2D4H44]  199.5 28.99 0 top
PU4601  RT3607CEGQW-GP  [WQFN56J6-G4D75H32]  72.68 225.19 180 top
PU4701  SM4378NSKPC-TRG-GP  [PPAK-8PH48]  51.39 167.69 90 top
PU4702  SM4378NSKPC-TRG-GP  [PPAK-8PH48]  51.39 204.77 90 top
PU4703  SM4378NSKPC-TRG-GP  [PPAK-8PH48]  51.39 211.11 90 top
PU4704  SM4378NSKPC-TRG-GP  [PPAK-8PH48]  51.39 139.6 90 top
PU4705  SM4504NHKPC-TRG-1-GP  [PPAK-8PH48]  65.43 198.46 0 top
PU4706  SM4504NHKPC-TRG-1-GP  [PPAK-8PH48]  56.89 198.46 0 top
PU4707  SM4504NHKPC-TRG-1-GP  [PPAK-8PH48]  65.43 133.39 0 top
PU4708  SM4378NSKPC-TRG-GP  [PPAK-8PH48]  51.39 189.39 90 top
PU4709  RT9624FGQW-GP  [DFN8F3-G2416H32]  48.6 195.91 180 top
PU4710  SM4504NHKPC-TRG-1-GP  [PPAK-8PH48]  65.43 176.73 0 top
PU4711  SM4504NHKPC-TRG-1-GP  [PPAK-8PH48]  56.89 176.74 0 top
PU4712  SM4378NSKPC-TRG-GP  [PPAK-8PH48]  51.39 161.37 90 top
PU4713  RT9624FGQW-GP  [DFN8F3-G2416H32]  48.47 173.94 180 top
PU4714  SM4504NHKPC-TRG-1-GP  [PPAK-8PH48]  56.89 155.07 0 top
PU4715  SM4504NHKPC-TRG-1-GP  [PPAK-8PH48]  65.43 155.06 0 top
PU4716  RT9624FGQW-GP  [DFN8F3-G2416H32]  46.62 218 180 top
PU4717  SM4504NHKPC-TRG-1-GP  [PPAK-8PH48]  56.89 133.39 0 top
PU4718  SM4378NSKPC-TRG-GP  [PPAK-8PH48]  51.39 146.03 90 top
PU4719  RT9624FGQW-GP  [DFN8F3-G2416H32]  48.47 152.4 180 top
PU4721  SM4378NSKPC-TRG-GP  [PPAK-8PH48]  51.39 183.01 90 top
PU4801  SM4504NHKPC-TRG-1-GP  [PPAK-8PH48]  128.48 213.74 90 top
PU4802  SM4378NSKPC-TRG-GP  [PPAK-8PH48]  102.91 227.7 0 top
PU4803  SM4378NSKPC-TRG-GP  [PPAK-8PH48]  109.24 227.7 0 top
PU4804  RT9624FGQW-GP  [DFN8F3-G2416H32]  88.02 215.81 180 top
PU4805  SM4504NHKPC-TRG-1-GP  [PPAK-8PH48]  96.71 222.33 270 top
PU4806  SM4504NHKPC-TRG-1-GP  [PPAK-8PH48]  96.7 213.73 270 top
PU4807  SM4378NSKPC-TRG-GP  [PPAK-8PH48]  122.22 227.7 0 top
PU4808  SM4378NSKPC-TRG-GP  [PPAK-8PH48]  115.92 227.7 0 top
PU4809  RT9624FGQW-GP  [DFN8F3-G2416H32]  130.67 232.17 180 top
PU4810  SM4504NHKPC-TRG-1-GP  [PPAK-8PH48]  129.5 222.32 90 top
PU5001  SM4504NHKPC-TRG-1-GP  [PPAK-8PH48]  221.88 132.52 0 top
PU5002  RT8207MZQW-GP-U  [QFN20-G1D75H32]  223.01 116.15 90 top
PU5003  SM4378NSKPC-TRG-GP  [PPAK-8PH48]  213.54 130.49 180 top
PU5101  RT8237CZQW-2-GP  [DFN10G3-G265175H32]  198.18 37.17 270 top
PU5102  SM4378NSKPC-TRG-GP  [PPAK-8PH48]  196.29 52.34 270 top
PU5103  SM4504NHKPC-TRG-1-GP  [PPAK-8PH48]  194.25 43.99 90 top
PU5201  SM4504NHKPC-TRG-1-GP  [PPAK-8PH48]  76.13 109.73 270 top
PU5202  NCP5230MNTWG-GP-U  [QFN16G3-G1D85-UH40]  55.13 106.09 0 top
PU5203  SM4378NSKPC-TRG-GP  [PPAK-8PH48]  74.1 101.22 90 top
PU5301  RT8237CZQW-2-GP  [DFN10G3-G265175H32]  117.68 94.85 180 top
PU5302  SM4378NSKPC-TRG-GP  [PPAK-8PH48]  112.72 104.87 180 top
PU5303  SM4504NHKPC-TRG-1-GP  [PPAK-8PH48]  120.98 106.95 0 top
Q1  2N7002EDW-2-GP  [SOT-363H44]  136.59 92.65 180 top
Q2  AO3418L-GP  [SOT23DGS2D8H50]  132.27 90.98 180 top
Q23  2N7002KDW-GP  [SOT-363H44]  237.5 31.28 270 top
Q25  2N7002KDW-GP  [SOT-363H44]  232.03 30.18 0 top
Q58  2N7002K-2-GP  [SOT23DGS2D4H44]  204.3 29.02 0 top
Q72  MBT3904DW1T1G-2-GP  [SOT-363H44]  227.84 219.07 0 top
Q73  MMBT3904-4-GP  [SOT23CBE2D4H44]  231.14 220.95 0 top
Q98  2N7002A-7-GP  [SOT23DGS2D4H48]  234.61 39.77 270 top
Q2002  LMBT3904LT1G-GP  [SOT23CBE2D4H44]  237.08 103.19 0 top
Q2004  2N7002H-GP  [SOT23DGS2D4H44]  174.35 32.72 90 top
Q2005  MMBT3906-4-GP  [SOT23CBE2D4H44]  195.32 17.38 180 top
Q2007  2N7002H-GP  [SOT23DGS2D4H44]  174.34 36.32 90 top
Q2601  LMBT3904LT1G-GP  [SOT23CBE2D4H44]  221.13 227.47 0 top
Q2602  MMBT3906-4-GP  [SOT23CBE2D4H44]  217.45 231.39 0 top
Q2603  MMBT3906-4-GP  [SOT23CBE2D4H44]  221.08 231.39 0 top
Q2604  MMBT3906-4-GP  [SOT23CBE2D4H44]  237.1 48.2 90 top
Q2605  MMBT3906-4-GP  [SOT23CBE2D4H44]  237.1 44.64 90 top
Q2606  LMBT3904LT1G-GP  [SOT23CBE2D4H44]  232.3 44.69 270 top
Q2702  MMBT3906-4-GP  [SOT23CBE2D4H44]  30.74 36.72 270 top
Q2703  MMBT3906-4-GP  [SOT23CBE2D4H44]  30.74 33.1 270 top
Q2704  MMBT3906-4-GP  [SOT23CBE2D4H44]  26.85 38.72 0 top
Q2705  MMBT3906-4-GP  [SOT23CBE2D4H44]  29.82 43.61 0 top
Q2901  HN1C03FU-GP  [SC70-6H48]  26.61 13.52 90 top
Q2902  HN1C03FU-GP  [SC70-6H48]  13.69 12.33 270 top
Q2903  LMBT3904LT1G-GP  [SOT23CBE2D4H44]  47.13 6.92 0 top
Q3001  HN1C03FU-GP  [SC70-6H48]  18.54 61.65 270 top
Q3002  HN1C03FU-GP  [SC70-6H48]  12.34 60.38 270 top
Q3003  HN1C03FU-GP  [SC70-6H48]  7.07 60.26 270 top
Q3103  MMDT3904-7-F-1-GP  [SOT-363H44]  33.6 80.34 180 top
Q3106  AO3419L-GP  [SOT23DGS2D8H50]  34.41 98.05 180 top
Q3107  LMBT3904LT1G-GP  [SOT23CBE2D4H44]  37.99 100.07 0 top
Q3109  AO3419L-GP  [SOT23DGS2D8H50]  79.35 34.1 180 top
Q3401  2N7002A-7-GP  [SOT23DGS2D4H48]  72.84 18.94 270 top
Q3402  2N7002A-7-GP  [SOT23DGS2D4H48]  76.96 46.13 90 top
Q3507  QM3004D-GP  [SMD-TO-252-DGS6698H99]  221.31 95.25 0 top
Q3508  AO3413L-GP  [SOT23DGS2D8H50]  213.74 102.06 0 top
Q3509  AO3413L-GP  [SOT23DGS2D8H50]  214.89 97.94 0 top
Q3512  2N7002A-7-GP  [SOT23DGS2D4H48]  222.19 89.79 90 top
Q3514  2N7002A-7-GP  [SOT23DGS2D4H48]  218.44 89.64 180 top
Q3515  MMBT3904-4-GP  [SOT23CBE2D4H44]  211.46 88.8 270 top
Q3516  2N7002A-7-GP  [SOT23DGS2D4H48]  227.03 91.34 0 top
Q3518  2N7002A-7-GP  [SOT23DGS2D4H48]  211.46 92.35 270 top
Q4301  2N7002A-7-GP  [SOT23DGS2D4H48]  214.54 190.3 90 top
Q4302  2N7002A-7-GP  [SOT23DGS2D4H48]  214.52 186.73 270 top
Q4303  2N7002A-7-GP  [SOT23DGS2D4H48]  214.52 195.92 90 top
Q4304  2N7002A-7-GP  [SOT23DGS2D4H48]  214.47 201.66 90 top
Q5601  2N7002K-1-GP  [SOT23DGS2D4H44]  21.14 228.3 180 top
Q5602  2N7002K-1-GP  [SOT23DGS2D4H44]  22.77 234.47 270 top
Q5603  2N7002DW-6-GP  [SOT-363H44]  21.59 223.5 0 top
Q5701  2N7002K-2-GP  [SOT23DGS2D4H44]  16.98 200.77 90 top
Q5702  MBT3904DW1T1G-2-GP  [SOT-363H44]  22.66 195.76 90 top
Q5703  2N7002KDW-1-GP  [SOT-363H44]  21.62 207.02 180 top
Q5704  2N7002KDW-1-GP  [SOT-363H44]  21.64 200.38 180 top
Q5705  DMP2130L-7-GP  [SOT23DGS2D4H48]  15.88 207.95 270 top
Q6401  2N7002A-7-GP  [SOT23DGS2D4H48]  202.08 19.89 0 top
Q6402  2N7002KDW-1-GP  [SOT-363H44]  210.52 14.78 270 top
Q6403  MMBT3906-4-GP  [SOT23CBE2D4H44]  198.37 22.2 270 top
Q6404  BSS138-7F-GP  [SOT23DGS2D4H44]  50.69 67.45 180 top
Q6405  MMBT3906-4-GP  [SOT23CBE2D4H44]  181.82 16.63 270 top
Q6406  2N7002A-7-GP  [SOT23DGS2D4H48]  178.05 16.64 0 top
Q6407  MMBT3906-4-GP  [SOT23CBE2D4H44]  186.56 17.53 270 top
Q6805  2N7002A-7-GP  [SOT23DGS2D4H48]  208.51 11.48 270 top
Q6806  MMBT3906-4-GP  [SOT23CBE2D4H44]  204.11 14.58 180 top
Q6807  2N7002A-7-GP  [SOT23DGS2D4H48]  235.71 34.67 90 top
Q9303  P5003QVG-1-GP  [SOIC8H79]  190.04 78.08 180 top
R62  100KR2J-1-GP  [R402H16]  217.14 210.21 270 top
R63  10KR2F-2-GP  [R402H16]  213.91 207.83 270 top
R64  10KR2J-3-GP  [R402H16]  232.28 27.18 90 top
R65  10KR2F-2-GP  [R402H16]  217.32 212.32 90 top
R73  0R2J-2-GP  [R402H16]  135.61 98.21 0 top
R74  0R0402-PAD-2-GP  [0R0402-PAD-1]  134.38 99.8 180 top
R76  0R0402-PAD-2-GP  [0R0402-PAD-1]  134.14 97.81 90 top
R77  100KR2J-1-GP  [R402H16]  134.98 89.09 0 top
R78  47KR2J-2-GP  [R402H16]  134.56 91.64 180 top
R79  10KR2J-3-GP  [R402H16]  34.67 94.53 180 top
R80  220R5J-GP  [R805H24]  76.33 32.84 180 top
R81  100KR2J-1-GP  [R402H16]  135.88 96.22 180 top
R82  100KR2J-1-GP  [R402H16]  136.01 89.09 0 top
R83  4K7R2J-2-GP  [R402H16]  135.42 87.61 90 top
R84  10KR2J-3-GP  [R402H16]  134.56 93.53 180 top
R85  0R0402-PAD-2-GP  [0R0402-PAD-1]  138.23 95.4 180 top
R91  10KR2J-3-GP  [R402H16]  219.66 50.71 180 top
R92  10KR2J-3-GP  [R402H16]  230.18 77.21 180 top
R93  10KR2J-3-GP  [R402H16]  216.87 48.76 270 top
R94  10KR2J-3-GP  [R402H16]  225.03 76.84 90 top
R95  10KR2J-3-GP  [R402H16]  206.57 64.78 270 top
R96  10KR2J-3-GP  [R402H16]  215.41 48.33 180 top
R97  10KR2J-3-GP  [R402H16]  206.57 65.84 270 top
R98  10KR2J-3-GP  [R402H16]  225.76 75.36 180 top
R99  10KR2J-3-GP  [R402H16]  224.71 75.36 180 top
R155  10KR2F-2-GP  [R402H16]  239.33 37.13 180 top
R243  10KR2J-3-GP  [R402H16]  64.99 5.94 180 top
R244  10KR2J-3-GP  [R402H16]  69.61 8.35 180 top
R302  24D9R2F-L-GP  [R402H16]  119.28 156 270 top
R389  100R2F-L1-GP-U  [R402H14]  217.66 53.17 270 top
R402  0R0402-PAD-2-GP  [0R0402-PAD-1]  80.99 231.85 90 top
R403  51R2F-2-GP  [R402H16]  81.79 138.05 270 top
R404  51R2J-2-GP  [R402H16]  58.25 88.04 0 top
R405  51R2J-2-GP  [R402H16]  233.58 221.2 180 top
R406  0R0402-PAD-2-GP  [0R0402-PAD-1]  80.38 228.32 0 top
R407  51R2F-2-GP  [R402H16]  81.79 140.59 270 top
R408  51R2F-2-GP  [R402H16]  83.57 142.11 0 top
R414  1KR2J-1-GP  [R402H16]  84.33 148.76 270 top
R415  49D9R2F-GP  [R402H16]  119.28 157.02 90 top
R416  1KR2J-1-GP  [R402H16]  85.04 144.48 270 top
R417  1KR2J-1-GP  [R402H16]  83.13 155.25 270 top
R418  1KR2J-1-GP  [R402H16]  85.04 145.5 270 top
R419  1KR2J-1-GP  [R402H16]  86.18 148.37 0 top
R420  1KR2J-1-GP  [R402H16]  84.33 149.78 270 top
R421  75R2F-2-GP  [R402H16]  79.46 226.21 180 top
R422  20R2J-3-GP  [R402H16]  130.22 105.05 180 top
R423  1KR2J-1-GP  [R402H16]  80.81 149.08 270 top
R424  1KR2J-1-GP  [R402H16]  85.67 154.05 270 top
R425  1KR2J-1-GP  [R402H16]  85.67 155.07 270 top
R426  1KR2J-1-GP  [R402H16]  81.61 145.78 270 top
R427  1KR2J-1-GP  [R402H16]  85.16 157.53 270 top
R428  1KR2J-1-GP  [R402H16]  80.81 150.1 270 top
R429  1KR2J-1-GP  [R402H16]  83.17 153.2 270 top
R430  1KR2J-1-GP  [R402H16]  83.13 156.26 270 top
R431  1KR2J-1-GP  [R402H16]  83.17 152.18 270 top
R432  1KR2J-1-GP  [R402H16]  84.22 147.25 270 top
R448  2K8R2F-GP  [R402H16]  118.5 30.41 270 top
R449  6K34R2F-GP  [R402H16]  120.4 30.4 270 top
R452  0R2J-2-GP  [R402H16]  62.36 117.16 270 top
R454  0R2J-2-GP  [R402H16]  59.94 118.81 270 top
R455  0R2J-2-GP  [R402H16]  59.9 117.21 270 top
R456  0R2J-2-GP  [R402H16]  62.35 118.47 270 top
R458  1KR2J-1-GP  [R402H16]  85.16 158.54 270 top
R467  100R2F-L1-GP-U  [R402H14]  82.35 212.52 90 top
R469  220R2J-L2-GP  [R402H16]  81.42 224.33 90 top
R470  56R2F-1-GP  [R402H16]  80.92 225.79 270 top
R471  100R2J-2-GP  [R402H14]  81.42 228.32 180 top
R472  0R2J-2-GP  [R402H16]  221.39 75.72 0 top
R473  0R2J-2-GP  [R402H16]  223.27 78.89 90 top
R474  10KR2J-3-GP  [R402H16]  125.1 32.41 0 top
R476  10KR2J-3-GP  [R402H16]  121.96 35.56 90 top
R477  10KR2J-3-GP  [R402H16]  238.46 221.66 180 top
R478  10KR2J-3-GP  [R402H16]  110.94 33.83 270 top
R479  10KR2J-3-GP  [R402H16]  239.65 218.68 180 top
R507  124R2F-U-GP  [R402H16]  233.6 187.04 90 top
R508  210R2F-L-GP  [R402H16]  233.6 188.08 270 top
R523  100KR2J-1-GP  [R402H16]  233.07 208.98 90 top
R524  100KR2J-1-GP  [R402H16]  233.03 215.95 0 top
R525  100KR2J-1-GP  [R402H16]  235.58 210.49 180 top
R530  100KR2J-1-GP  [R402H16]  236.23 215.93 0 top
R531  47KR2J-2-GP  [R402H16]  233.04 210.02 270 top
R532  0R2J-2-GP  [R402H16]  238.83 215.88 90 top
R533  0R2J-2-GP  [R402H16]  239.27 216.94 90 top
R544  2K2R2J-2-GP  [R402H16]  210.9 211.2 90 top
R650  0R3J-0-U-GP  [R603H22]  204.77 26.52 90 top
R652  0R2J-2-GP  [R402H16]  238.12 33.83 0 top
R653  0R2J-2-GP  [R402H16]  235.13 30.78 180 top
R655  10KR2J-3-GP  [R402H16]  201.86 28.16 0 top
R695  0R0402-PAD-2-GP  [0R0402-PAD-1]  215.37 212.01 90 top
R696  0R0402-PAD-2-GP  [0R0402-PAD-1]  239.65 224.33 180 top
R699  0R0402-PAD-2-GP  [0R0402-PAD-1]  210.06 216.13 90 top
R702  20R2J-3-GP  [R402H16]  133.56 105.83 0 top
R703  24D9R2F-L-GP  [R402H16]  119.29 154.97 90 top
R704  0R3J-0-U-GP  [R603H22]  133.12 88.39 90 top
R802  0R0402-PAD-2-GP  [0R0402-PAD-1]  131.53 154.87 270 bottom
R804  0R0402-PAD-2-GP  [0R0402-PAD-1]  124.79 91.75 270 top
R805  0R0402-PAD-2-GP  [0R0402-PAD-1]  124.78 92.96 270 top
R806  0R2J-2-GP  [R402H16]  116.95 174.92 180 bottom
R807  0R2J-2-GP  [R402H16]  130.71 174.65 0 bottom
R811  0R2J-2-GP  [R402H16]  132.11 168.96 270 bottom
R813  1KR2J-1-GP  [R402H16]  69.61 6.44 0 top
R814  1KR2J-1-GP  [R402H16]  63.95 5.95 180 top
R866  10KR2J-3-GP  [R402H16]  71.73 45.14 0 top
R879  1KR2J-1-GP  [R402H16]  225.31 221.41 270 top
R884  10KR2J-3-GP  [R402H16]  225.68 218.31 180 top
R888  100KR2J-1-GP  [R402H16]  238.48 212.87 180 top
R901  560R2J-3-GP  [R402H16]  85.09 140.97 270 top
R902  20R2F-GP  [R402H16]  131.73 106.13 180 top
R919  0R0402-PAD-2-GP  [0R0402-PAD-1]  112.15 67.13 90 top
R920  0R0402-PAD-2-GP  [0R0402-PAD-1]  112.15 66.12 90 top
R921  0R0402-PAD-2-GP  [0R0402-PAD-1]  112.15 63.37 90 top
R922  0R0402-PAD-2-GP  [0R0402-PAD-1]  112.16 62.34 90 top
R923  0R0402-PAD-2-GP  [0R0402-PAD-1]  112.16 59.59 90 top
R924  0R0402-PAD-2-GP  [0R0402-PAD-1]  112.17 58.56 90 top
R925  0R0402-PAD-2-GP  [0R0402-PAD-1]  112.17 55.82 90 top
R926  0R0402-PAD-2-GP  [0R0402-PAD-1]  112.17 54.8 90 top
R979  8K2R2F-1-GP  [R402H16]  228.8 221.87 0 top
R980  8K2R2F-1-GP  [R402H16]  228.78 223.52 90 top
R982  0R0402-PAD-2-GP  [0R0402-PAD-1]  220.98 218.69 90 top
R983  0R0402-PAD-2-GP  [0R0402-PAD-1]  218.39 213.79 180 top
R984  0R0402-PAD-2-GP  [0R0402-PAD-1]  230.23 223.98 0 top
R985  0R2J-2-GP  [R402H16]  223.77 220.27 0 top
R986  0R2J-2-GP  [R402H16]  220.98 217.55 90 top
R987  0R2J-2-GP  [R402H16]  220.95 216 90 top
R988  0R2J-2-GP  [R402H16]  221.62 220.17 0 top
R989  0R2J-2-GP  [R402H16]  222.71 220.28 0 top
R990  0R2J-2-GP  [R402H16]  227.2 221.49 270 top
R991  10KR2J-3-GP  [R402H16]  229.64 216.74 90 top
R1009  330R2J-3-GP  [R402H16]  237.5 38.64 90 top
R1117  240R2F-1-GP  [R402H16]  170.85 161.87 90 top
R1118  240R2F-1-GP  [R402H16]  209.55 162.29 270 top
R1119  240R2F-1-GP  [R402H16]  209.52 163.32 270 top
R1123  24D9R2F-L-GP  [R402H16]  148.59 224.41 0 top
R1125  0R0402-PAD-2-GP  [0R0402-PAD-1]  209.5 228.8 180 top
R1126  2R2F-GP  [R402H16]  148.46 226.95 90 top
R1129  1KR2F-3-GP  [R402H16]  210.97 228.6 270 top
R1130  1KR2F-3-GP  [R402H16]  210.97 227.53 270 top
R1132  240R2F-1-GP  [R402H16]  170.85 162.89 90 top
R1201  0R0402-PAD-2-GP  [0R0402-PAD-1]  210.92 220.58 180 top
R1204  1KR2F-3-GP  [R402H16]  211.46 219.05 270 top
R1205  1KR2F-3-GP  [R402H16]  209.98 218.59 180 top
R1206  2R2F-GP  [R402H16]  145.49 226.92 90 top
R1207  24D9R2F-L-GP  [R402H16]  145.92 224.43 0 top
R1502  10KR2F-2-GP  [R402H16]  154.59 25.11 270 top
R1504  10KR2F-2-GP  [R402H16]  168.74 42.49 0 top
R1505  10KR2F-2-GP  [R402H16]  170.92 53.68 90 top
R1506  10KR2F-2-GP  [R402H16]  195.4 22.99 270 top
R1510  1MR2J-1-GP  [R402H16]  144.29 29.15 0 top
R1520  0R0402-PAD-2-GP  [0R0402-PAD-1]  155.05 23.48 180 top
R1521  30R2J-1-GP  [R402H16]  154.43 33.86 90 top
R1532  10KR2J-3-GP  [R402H16]  114.23 52.05 90 top
R1534  10KR2J-3-GP  [R402H16]  196.63 29.93 270 top
R1535  10KR2J-3-GP  [R402H16]  221.83 6.55 270 top
R1536  10KR2J-3-GP  [R402H16]  221.83 7.58 270 top
R1601  10KR2J-3-GP  [R402H16]  167.89 54.86 270 top
R1604  113R2F-GP  [R402H16]  136.27 46.48 270 top
R1605  1KR2J-1-GP  [R402H16]  135.18 43.65 270 top
R1606  1KR2J-1-GP  [R402H16]  133.6 46.48 90 top
R1608  100R2F-L1-GP-U  [R402H14]  146.48 66.84 0 top
R1610  100KR2F-L1-GP  [R402H16]  132.8 30.71 90 top
R1613  2K2R2J-2-GP  [R402H16]  134.29 33.73 270 top
R1614  2K2R2J-2-GP  [R402H16]  134.28 32.69 270 top
R1615  10KR2J-3-GP  [R402H16]  170.49 56.81 90 top
R1616  10KR2J-3-GP  [R402H16]  167.89 56.26 270 top
R1617  10KR2J-3-GP  [R402H16]  167.95 53.11 90 top
R1618  10KR2J-3-GP  [R402H16]  167.97 52.06 270 top
